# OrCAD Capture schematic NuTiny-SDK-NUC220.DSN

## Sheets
1 PAGE0_PLACEMENT: title: Nuvoton NU_TINY_220; rev: 1.0; note: 8051 ISP-ICP Gang Programmer, ¥ÀªO.DSN
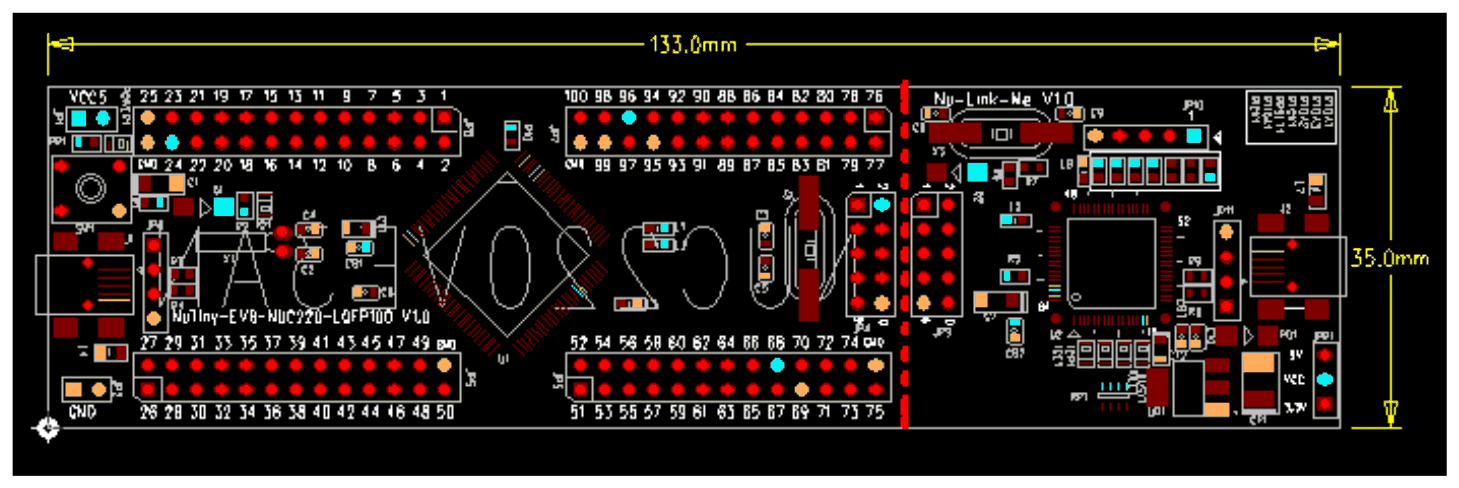
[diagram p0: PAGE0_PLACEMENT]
2 PAGE1_DEMO_CIRCUIT: size A2; rev: 1.1
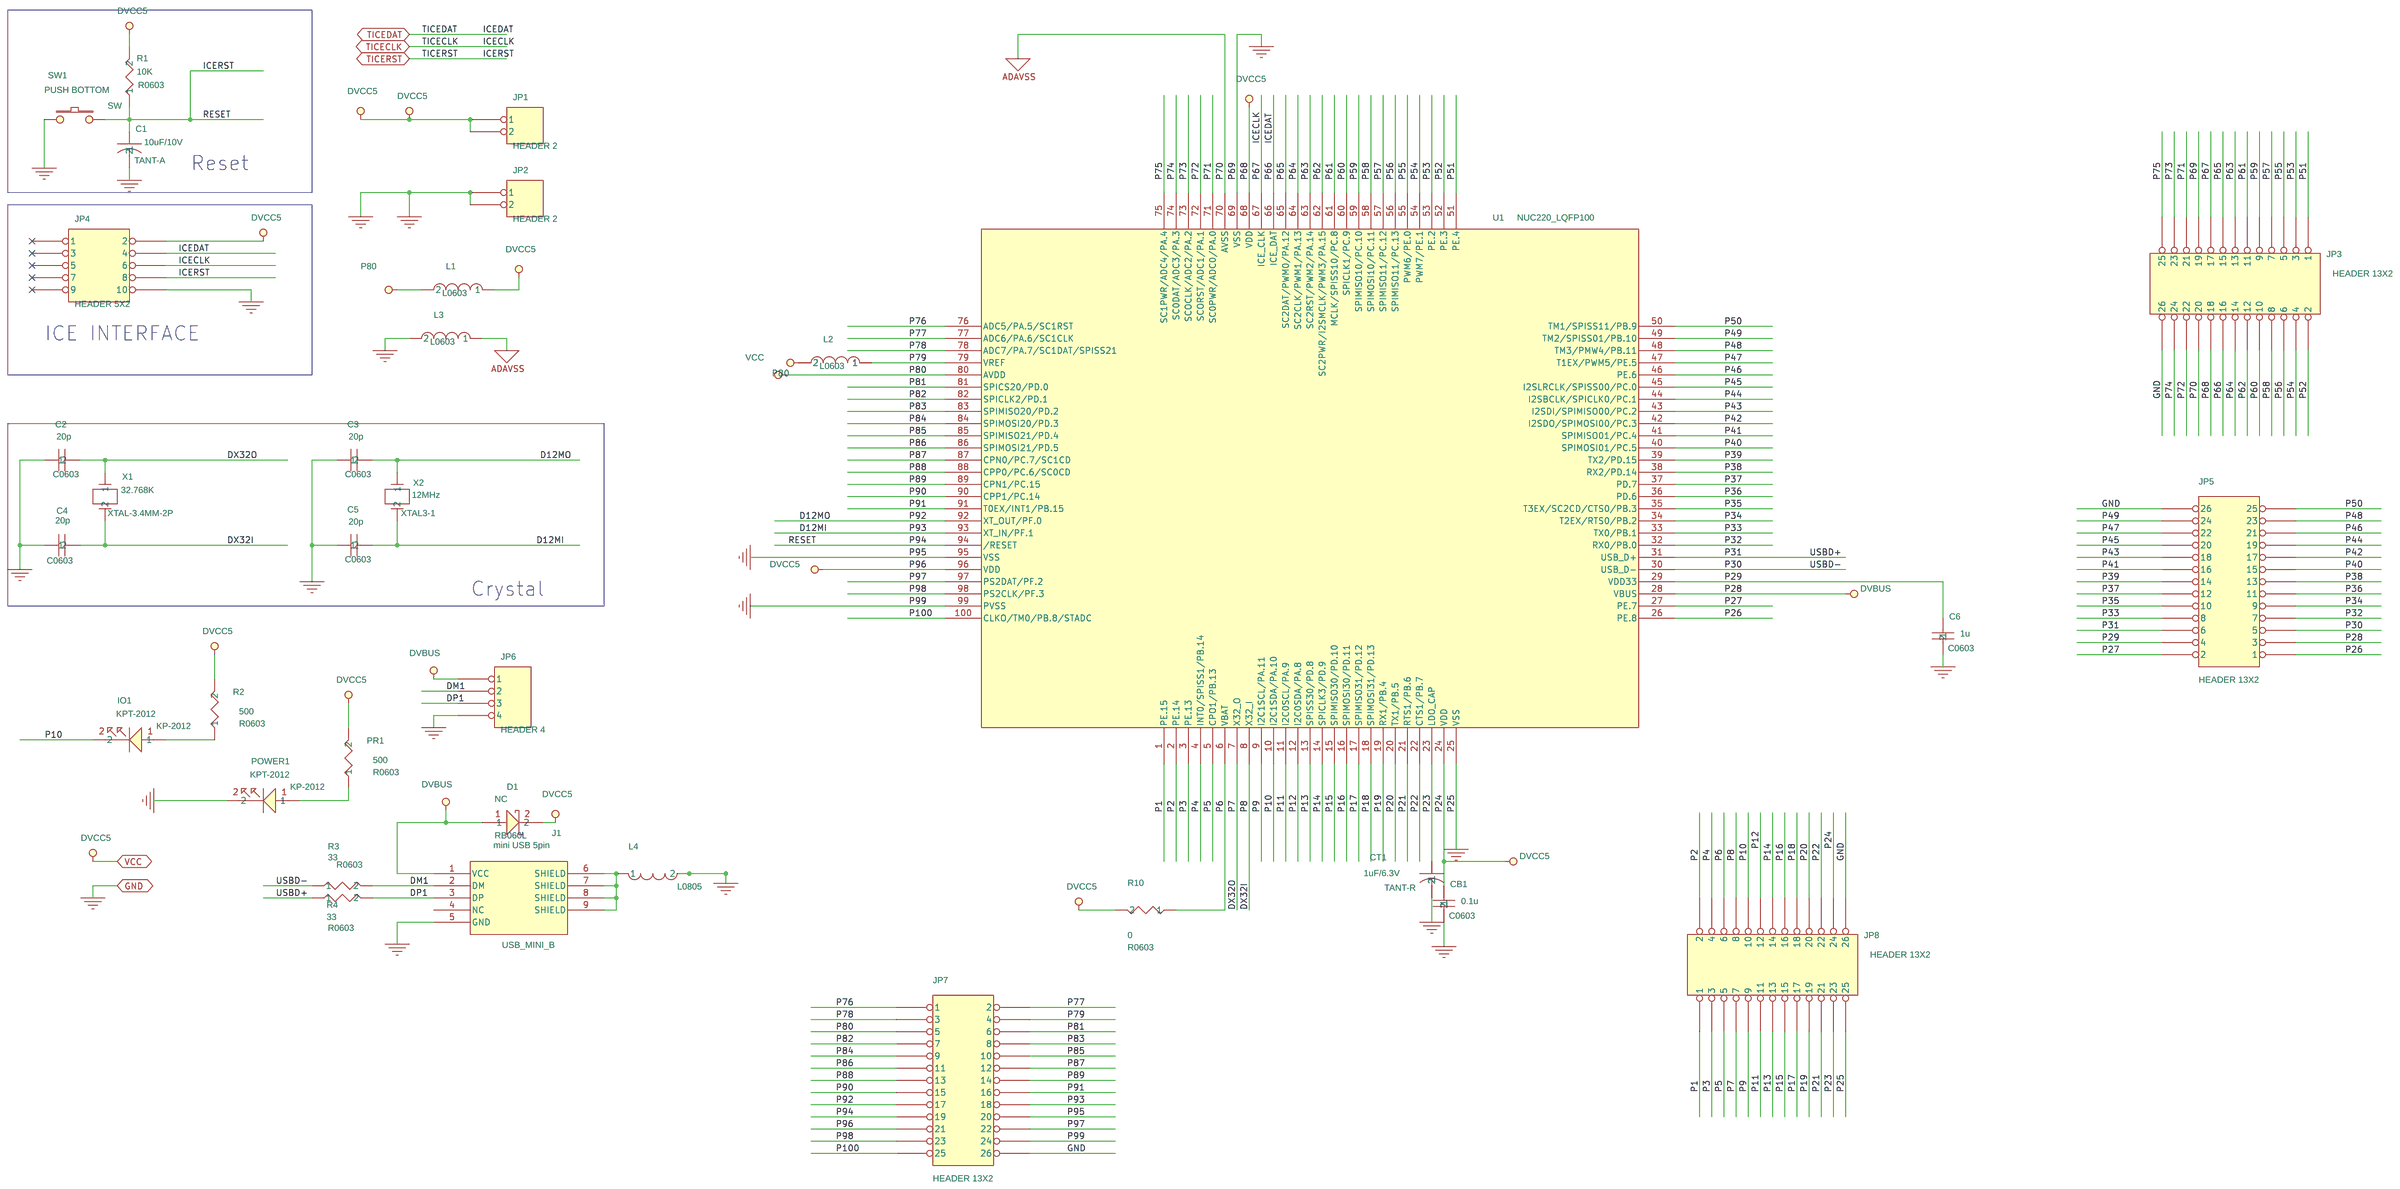
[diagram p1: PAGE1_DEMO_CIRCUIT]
3 PAGE2_ICE_CIRCUIT: size Custom
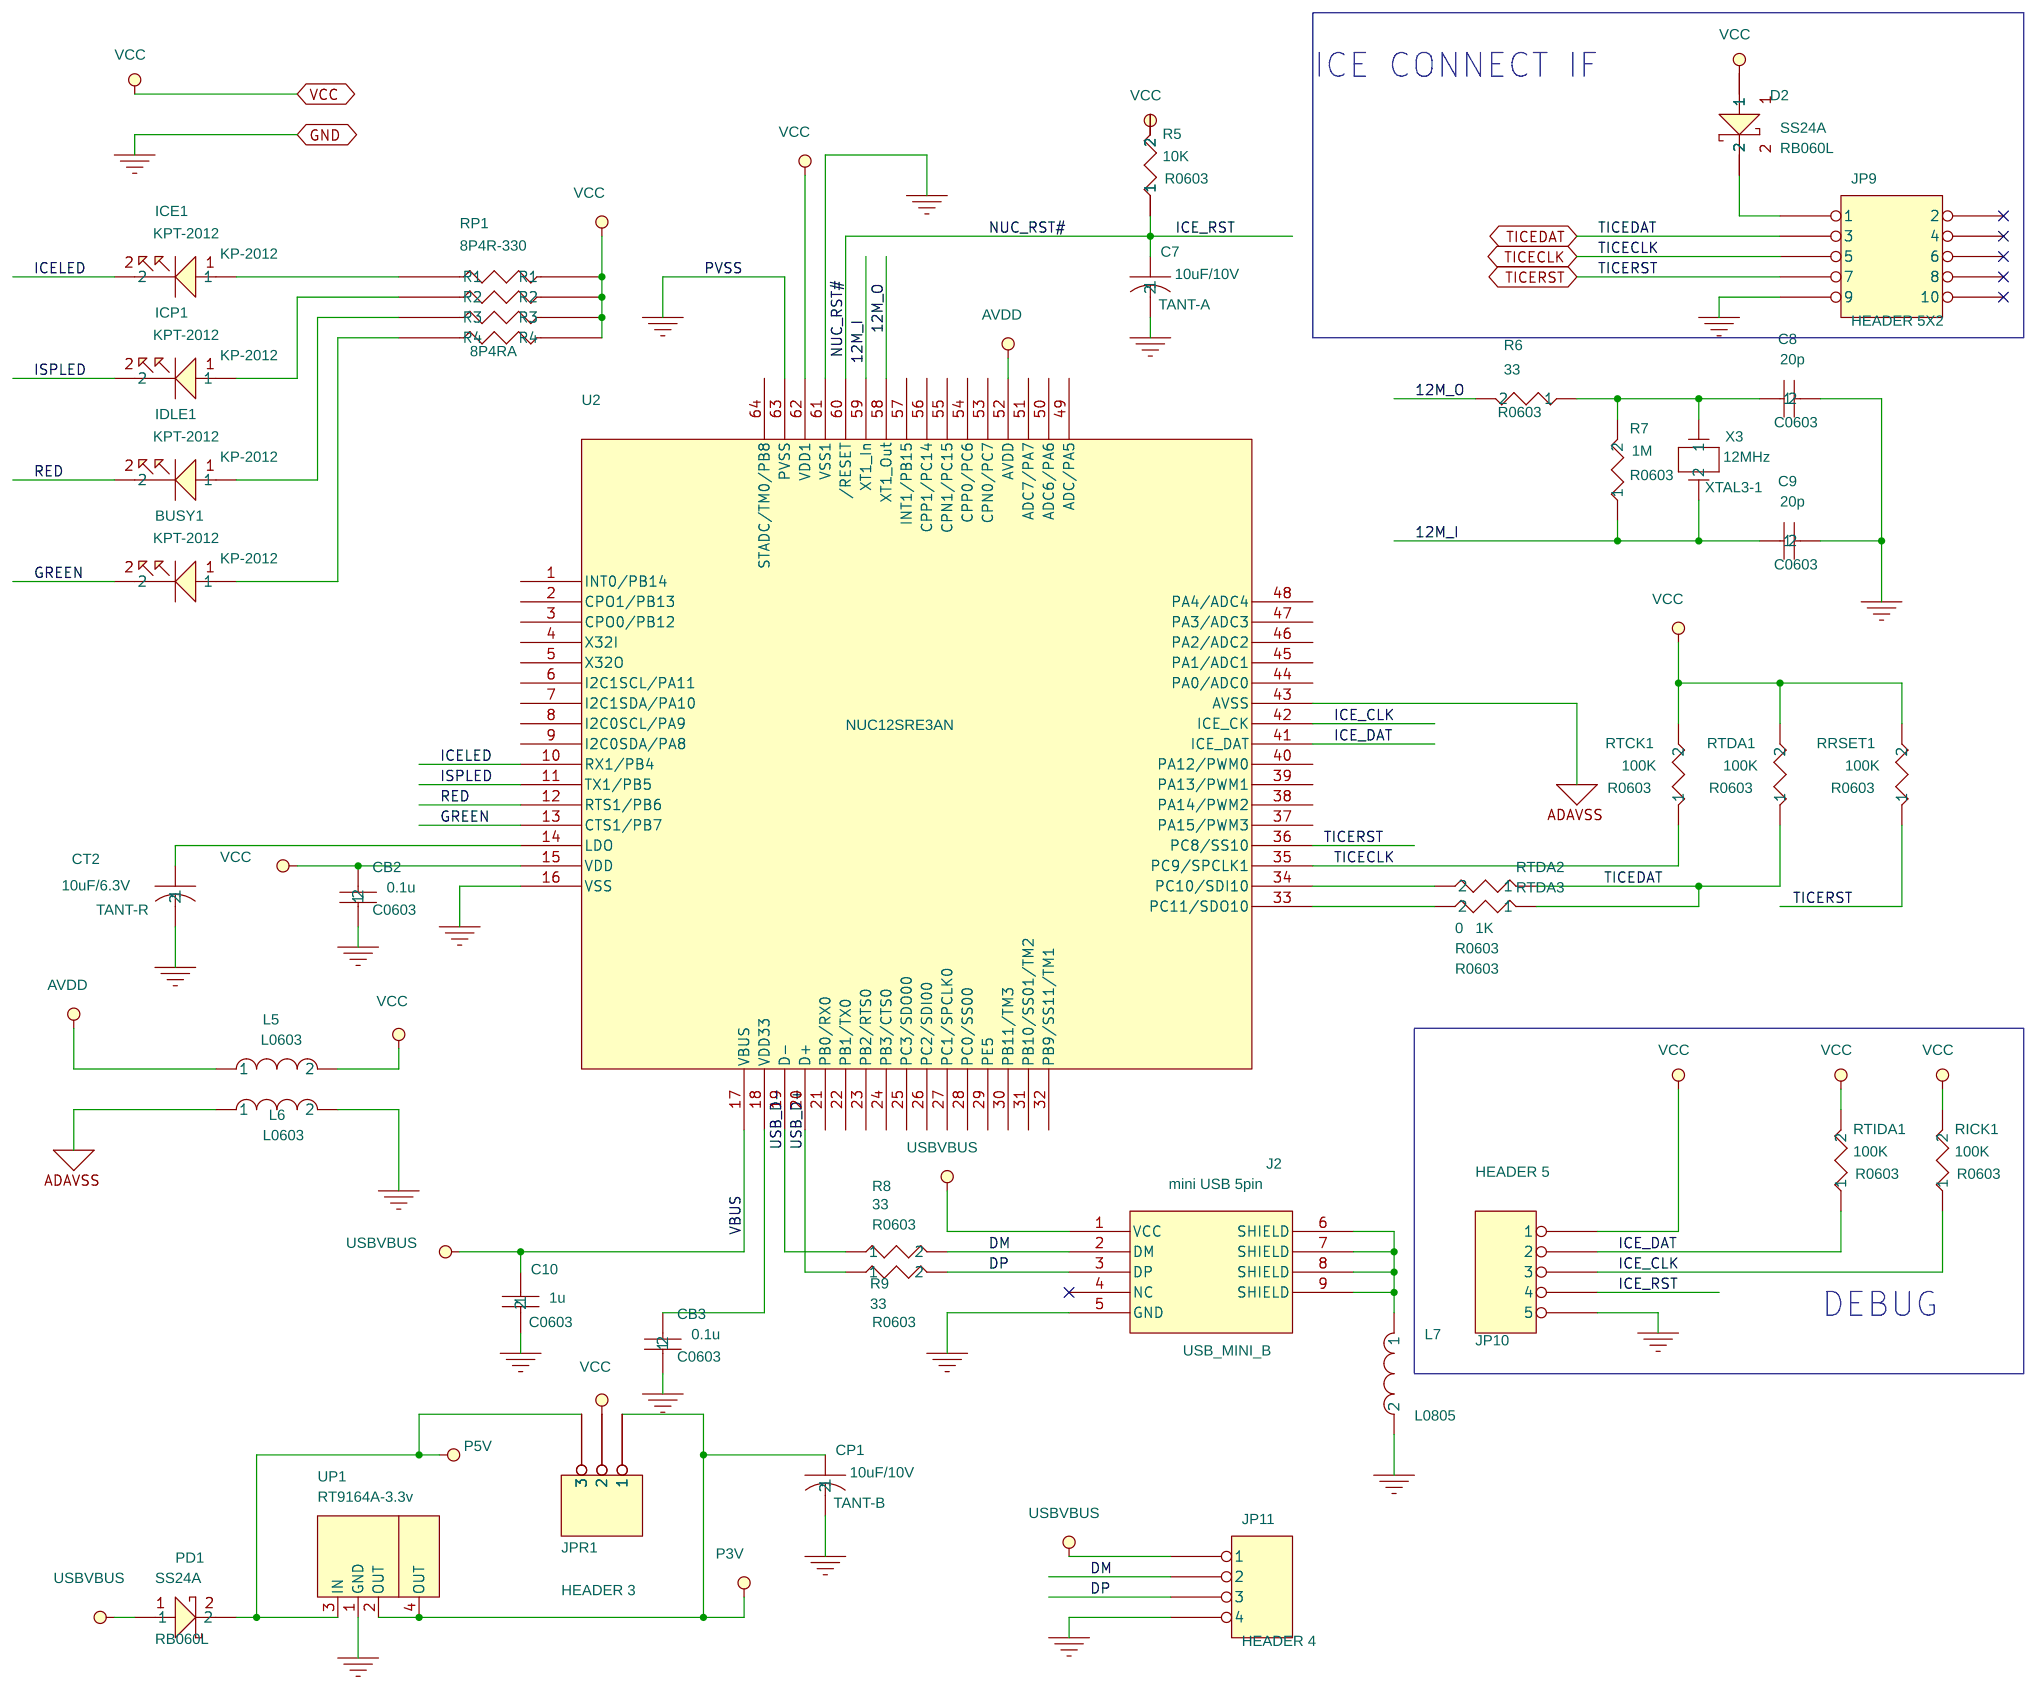
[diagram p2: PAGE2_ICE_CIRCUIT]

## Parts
sheet PAGE1_DEMO_CIRCUIT
C1  10uF/10V  [TANT-A]
C2  20p  [C0603]
C3  20p  [C0603]
C4  20p  [C0603]
C5  20p  [C0603]
C6  1u  [C0603]
CB1  0.1u  [C0603]
CT1  1uF/6.3V  [TANT-R]
D1  NC  [RB060L]
IO1  KPT-2012  [KP-2012]
J1  mini USB 5pin  [USB_MINI_B]
JP1  HEADER 2
JP2  HEADER 2
JP3  HEADER 13X2
JP4  HEADER 5X2
JP5  HEADER 13X2
JP6  HEADER 4
JP7  HEADER 13X2
JP8  HEADER 13X2
L1  FERRITE BEAD  [L0603]
L2  FERRITE BEAD  [L0603]
L3  FERRITE BEAD  [L0603]
L4  FERRITE BEAD  [L0805]
POWER1  KPT-2012  [KP-2012]
PR1  500  [R0603]
R1  10K  [R0603]
R2  500  [R0603]
R3  33  [R0603]
R4  33  [R0603]
R10  0  [R0603]
SW1  PUSH BOTTOM  [SW]
U1  NUC220_LQFP100  [LQFP-SOCKET-100]
X1  32.768K  [XTAL-3.4MM-2P]
X2  12MHz  [XTAL3-1]
sheet PAGE2_ICE_CIRCUIT
BUSY1  KPT-2012  [KP-2012]
C7  10uF/10V  [TANT-A]
C8  20p  [C0603]
C9  20p  [C0603]
C10  1u  [C0603]
CB2  0.1u  [C0603]
CB3  0.1u  [C0603]
CP1  10uF/10V  [TANT-B]
CT2  10uF/6.3V  [TANT-R]
D2  SS24A  [RB060L]
ICE1  KPT-2012  [KP-2012]
ICP1  KPT-2012  [KP-2012]
IDLE1  KPT-2012  [KP-2012]
J2  mini USB 5pin  [USB_MINI_B]
JP9  HEADER 5X2
JP10  HEADER 5
JP11  HEADER 4
JPR1  HEADER 3
L5  FERRITE BEAD  [L0603]
L6  FERRITE BEAD  [L0603]
L7  FERRITE BEAD  [L0805]
PD1  SS24A  [RB060L]
R5  10K  [R0603]
R6  33  [R0603]
R7  1M  [R0603]
R8  33  [R0603]
R9  33  [R0603]
RICK1  100K  [R0603]
RP1  8P4R-330  [8P4RA]
RRSET1  100K  [R0603]
RTCK1  100K  [R0603]
RTDA1  100K  [R0603]
RTDA2  0  [R0603]
RTDA3  1K  [R0603]
RTIDA1  100K  [R0603]
U2  NUC12SRE3AN  [NCU120_LQFP_64]
UP1  RT9164A-3.3v  [SOT-223-1]
X3  12MHz  [XTAL3-1]

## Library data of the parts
C1 CT2 = CAP_1
C2 C9 = CAP-C: Package: 0603
C3 = CAP-C_5: Package: 0603
C4 C10 = CAP-C_1: Package: 0603
C5 CB2 = CAP-C_2: Package: 0603
C6 C8 = CAP-C_4: Package: 0603
CB1 CB3 = CAP-C_3: Package: 0603
C7 CT1 = CAP
D1 D2 = DIODE_SCHOTTKY_6: Package: SOD-1231; Vendor: ROHM
ICP1 IO1 = LED_0_1: Vendor: Kingbright
J1 J2 = 4X1_HEADER_5
JP1 = HEADER_2_1
JP2 = HEADER_2
JP3 = HEADER_13X2
JP4 JP9 = HEADER_5X2
JP5 = HEADER_13X2_3
JP6 JP11 = HEADER_4
JP7 = HEADER_13X2_1
JP8 = HEADER_13X2_2
L1 L5 = INDUCTOR
L2 = INDUCTOR_1
L3 = INDUCTOR_3
L4 = INDUCTOR_2: Package: 0805
IDLE1 POWER1 = LED_0: Vendor: Kingbright
PR1 RTIDA1 = R_0_1: Package: 0603
R1 R8 = R_0_2: Package: 0603
R2 RTDA1 = R_0_4: Package: 0603
R3 RTCK1 = R_0: Package: 0603
R4 R7 = R_0_3: Package: 0603
R5 R10 = R_0_5: Package: 0603
SW1 = SW_PUSHBUTTON: Package: DIP PUSH BOTTOM
U1 = Nano100_0
X1 = CRYSTAL_1
X2 X3 = CRYSTAL
BUSY1 = LED_0_2: Vendor: Kingbright
CP1 = CAP_2: Package: TANT-R
ICE1 = LED_0_3: Vendor: Kingbright
JP10 = HEADER_5
JPR1 = HEADER_3
L6 = INDUCTOR_2
L7 = INDUCTOR_1: Package: 0805
PD1 = DIODE_SCHOTTKY_6_1: Package: SOD-1231; Vendor: ROHM
R6 = R_0_10: Package: 0603
R9 = R_0_6: Package: 0603
RICK1 = R_0_11: Package: 0603
RP1 = R-PACK8_0
RRSET1 = R_0_7: Package: 0603
RTDA2 = R_0_9: Package: 0603
RTDA3 = R_0_8: Package: 0603
U2 = NCU120_LQFP_64
UP1 = TO-247_Regulator_10

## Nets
AVDD: L5.1 U2.52(AVDD)
DVBUS: D1.1 J1.1(VCC) JP5.3 JP6.1 U1.28(VBUS)
GND: C1.2 C2.1 C3.1 C4.1 C5.1 C6.2 C7.2 C8.2 C9.2 C10.2 CB1.2 CB2.1 CB3.1 CP1.2 CT1.2 CT2.2 J1.5(GND) J2.5(GND) JP2.1 JP2.2 JP3.19 JP3.26 JP4.10 JP5.26 JP6.4 JP7.20 JP7.24 JP7.26 JP8.25 JP8.26 JP9.9 JP10.5 JP11.4 L3.2 L4.2 L6.2 L7.2 POWER1.2 SW1.1 U1.25(VSS) U1.69(VSS) U1.95(VSS) U1.99(PVSS) U2.16(VSS) U2.61(VSS1) U2.63(PVSS) UP1.1(GND)
P3V: CP1.1 JPR1.1 UP1.2(OUT) UP1.4(OUT)
P5V: JPR1.3 PD1.2 UP1.3(IN)
VCC: CB1.1 CB2.2 D1.2 D2.1 JP1.1 JP1.2 JP3.18 JP4.2 JP7.21 JP8.24 JP10.1 JPR1.2 L1.1 L2.2 L5.2 PR1.2 R1.2 R2.2 R5.2 R10.2 RICK1.2 RP1.2(R1) RP1.4(R2) RP1.6(R3) RP1.8(R4) RRSET1.2 RTCK1.2 RTDA1.2 RTIDA1.2 U1.24(VDD) U1.68(VDD) U1.96(VDD) U2.15(VDD) U2.62(VDD1)
12M_I: C9.1 R7.1 U2.59(XT1_In) X3.2
12M_O: R6.2 U2.58(XT1_Out)
ADAVSS: L6.1 U2.43(AVSS)
D12MI: C5.2 JP7.18 U1.93(XT_IN/PF.1) X2.2
D12MO: C3.2 JP7.17 U1.92(XT_OUT/PF.0) X2.1
DAVDD: JP7.5 L1.2 U1.80(AVDD)
DAVSS: JP3.20 L3.1 U1.70(AVSS)
DM: J2.2(DM) JP11.2 R8.2
DM1: J1.2(DM) JP6.2 R3.2
DP: J2.3(DP) JP11.3 R9.2
DP1: J1.3(DP) JP6.3 R4.2
DX32I: C4.2 JP8.8 U1.8(X32_I) X1.2
DX32O: C2.2 JP8.7 U1.7(X32_O) X1.1
GREEN: BUSY1.2 U2.13(CTS1/PB7)
ICE_CLK: JP10.3 RICK1.1 U2.42(ICE_CK)
ICE_DAT: JP10.2 RTIDA1.1 U2.41(ICE_DAT)
ICE_RST: C7.1 JP10.4 R5.1 U2.60(/RESET)
ICELED: ICE1.2 U2.10(RX1/PB4)
ISPLED: ICP1.2 U2.11(TX1/PB5)
P1: JP8.1 U1.1(PE.15)
P2: JP8.2 U1.2(PE.14)
P3: JP8.3 U1.3(PE.13)
P4: JP8.4 U1.4(INT0/SPISS1/PB.14)
P5: JP8.5 U1.5(CPO1/PB.13)
P6: JP8.6 R10.1 U1.6(VBAT)
P9: JP8.9 U1.9(I2C1SCL/PA.11)
P10: IO1.2 JP8.10 U1.10(I2C1SDA/PA.10)
P11: JP8.11 U1.11(I2C0SCL/PA.9)
P12: JP8.12 U1.12(I2C0SDA/PA.8)
P13: JP8.13 U1.13(SPISS30/PD.8)
P14: JP8.14 U1.14(SPICLK3/PD.9)
P15: JP8.15 U1.15(SPIMISO30/PD.10)
P16: JP8.16 U1.16(SPIMOSI30/PD.11)
P17: JP8.17 U1.17(SPIMISO31/PD.12)
P18: JP8.18 U1.18(SPIMOSI31/PD.13)
P19: JP8.19 U1.19(RX1/PB.4)
P20: JP8.20 U1.20(TX1/PB.5)
P21: JP8.21 U1.21(RTS1/PB.6)
P22: JP8.22 U1.22(CTS1/PB.7)
P23: CT1.1 JP8.23 U1.23(LDO_CAP)
P26: JP5.1 U1.26(PE.8)
P27: JP5.2 U1.27(PE.7)
P29: C6.1 JP5.4 U1.29(VDD33)
P30: JP5.5 R3.1 U1.30(USB_D-)
P31: JP5.6 R4.1 U1.31(USB_D+)
P32: JP5.7 U1.32(RX0/PB.0)
P33: JP5.8 U1.33(TX0/PB.1)
P34: JP5.9 U1.34(T2EX/RTS0/PB.2)
P35: JP5.10 U1.35(T3EX/SC2CD/CTS0/PB.3)
P36: JP5.11 U1.36(PD.6)
P37: JP5.12 U1.37(PD.7)
P38: JP5.13 U1.38(RX2/PD.14)
P39: JP5.14 U1.39(TX2/PD.15)
P40: JP5.15 U1.40(SPIMOSI01/PC.5)
P41: JP5.16 U1.41(SPIMISO01/PC.4)
P42: JP5.17 U1.42(I2SDO/SPIMOSI00/PC.3)
P43: JP5.18 U1.43(I2SDI/SPIMISO00/PC.2)
P44: JP5.19 U1.44(I2SBCLK/SPICLK0/PC.1)
P45: JP5.20 U1.45(I2SLRCLK/SPISS00/PC.0)
P46: JP5.21 U1.46(PE.6)
P47: JP5.22 U1.47(T1EX/PWM5/PE.5)
P48: JP5.23 U1.48(TM3/PMW4/PB.11)
P49: JP5.24 U1.49(TM2/SPISS01/PB.10)
P50: JP5.25 U1.50(TM1/SPISS11/PB.9)
P51: JP3.1 U1.51(PE.4)
P52: JP3.2 U1.52(PE.3)
P53: JP3.3 U1.53(PE.2)
P54: JP3.4 U1.54(PWM7/PE.1)
P55: JP3.5 U1.55(PWM6/PE.0)
P56: JP3.6 U1.56(SPIMISO11/PC.13)
P57: JP3.7 U1.57(SPIMISO11/PC.12)
P58: JP3.8 U1.58(SPIMOSI10/PC.11)
P59: JP3.9 U1.59(SPIMISO10/PC.10)
P60: JP3.10 U1.60(SPICLK1/PC.9)
P61: JP3.11 U1.61(MCLK/SPISS10/PC.8)
P62: JP3.12 U1.62(SC2PWR/I2SMCLK/PWM3/PA.15)
P63: JP3.13 U1.63(SC2RST/PWM2/PA.14)
P64: JP3.14 U1.64(SC2CLK/PWM1/PA.13)
P65: JP3.15 U1.65(SC2DAT/PWM0/PA.12)
P71: JP3.21 U1.71(SC0PWR/ADC0/PA.0)
P72: JP3.22 U1.72(SCORST/ADC1/PA.1)
P73: JP3.23 U1.73(SCOCLK/ADC2/PA.2)
P74: JP3.24 U1.74(SC0DAT/ADC3/PA.3)
P75: JP3.25 U1.75(SC1PWR/ADC4/PA.4)
P76: JP7.1 U1.76(ADC5/PA.5/SC1RST)
P77: JP7.2 U1.77(ADC6/PA.6/SC1CLK)
P78: JP7.3 U1.78(ADC7/PA.7/SC1DAT/SPISS21)
P79: JP7.4 L2.1 U1.79(VREF)
P81: JP7.6 U1.81(SPICS20/PD.0)
P82: JP7.7 U1.82(SPICLK2/PD.1)
P83: JP7.8 U1.83(SPIMISO20/PD.2)
P84: JP7.9 U1.84(SPIMOSI20/PD.3)
P85: JP7.10 U1.85(SPIMISO21/PD.4)
P86: JP7.11 U1.86(SPIMOSI21/PD.5)
P87: JP7.12 U1.87(CPN0/PC.7/SC1CD)
P88: JP7.13 U1.88(CPP0/PC.6/SC0CD)
P89: JP7.14 U1.89(CPN1/PC.15)
P90: JP7.15 U1.90(CPP1/PC.14)
P91: JP7.16 U1.91(T0EX/INT1/PB.15)
P97: JP7.22 U1.97(PS2DAT/PF.2)
P98: JP7.23 U1.98(PS2CLK/PF.3)
P100: JP7.25 U1.100(CLKO/TM0/PB.8/STADC)
RED: IDLE1.2 U2.12(RTS1/PB6)
TICECLK: JP3.17 JP4.6 JP9.5 RTCK1.1 U1.67(ICE_CLK) U2.35(PC9/SPCLK1)
TICEDAT: JP3.16 JP4.4 JP9.3 RTDA1.1 RTDA2.1 RTDA3.1 U1.66(ICE_DAT)
TICERST: C1.1 JP4.8 JP7.19 JP9.7 R1.1 RRSET1.1 SW1.2 U1.94(/RESET) U2.36(PC8/SS10)
USB_D+: R9.1 U2.20(D+)
USB_D-: R8.1 U2.19(D-)
USBVBUS: C10.1 J2.1(VCC) JP11.1 PD1.1 U2.17(VBUS)
N00874: BUSY1.1 RP1.7(R4)
N00882: IDLE1.1 RP1.5(R3)
N00906: ICE1.1 RP1.1(R1)
N00938: ICP1.1 RP1.3(R2)
N07267: C8.1 R6.1 R7.2 X3.1
N16793024: D2.2 JP9.1
N16796086: J2.6(SHIELD) J2.7(SHIELD) J2.8(SHIELD) J2.9(SHIELD) L7.1
N16812063: CT2.1 U2.14(LDO)
N16812255: CB3.2 U2.18(VDD33)
N16812354: RTDA2.2 U2.34(PC10/SDI10)
N16812376: RTDA3.2 U2.33(PC11/SDO10)
N16823268: J1.6(SHIELD) J1.7(SHIELD) J1.8(SHIELD) J1.9(SHIELD) L4.1
N16829506: IO1.1 R2.1
N16831459: POWER1.1 PR1.1

Not connected (* = marked no-connect by the designer): J1 4(NC); J2 4(NC)*; JP4 1* 3* 5* 7* 9*; JP9 2* 4* 6* 8* 10*; U2 1(INT0/PB14) 2(CPO1/PB13) 3(CPO0/PB12) 4(X32I) 5(X32O) 6(I2C1SCL/PA11) 7(I2C1SDA/PA10) 8(I2C0SCL/PA9) 9(I2C0SDA/PA8) 21(PB0/RX0) 22(PB1/TX0) 23(PB2/RTS0) 24(PB3/CTS0) 25(PC3/SDO00) 26(PC2/SDI00) 27(PC1/SPCLK0) 28(PC0/SS00) 29(PE5) 30(PB11/TM3) 31(PB10/SS01/TM2) 32(PB9/SS11/TM1) 37(PA15/PWM3) 38(PA14/PWM2) 39(PA13/PWM1) 40(PA12/PWM0) 44(PA0/ADC0) 45(PA1/ADC1) 46(PA2/ADC2) 47(PA3/ADC3) 48(PA4/ADC4) 49(ADC/PA5) 50(ADC6/PA6) 51(ADC7/PA7) 53(CPN0/PC7) 54(CPP0/PC6) 55(CPN1/PC15) 56(CPP1/PC14) 57(INT1/PB15) 64(STADC/TM0/PB8)

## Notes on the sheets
sheet 2
- Reset
- ICE INTERFACE
- Crystal
sheet 3
- ICE CONNECT IF
- DEBUG
